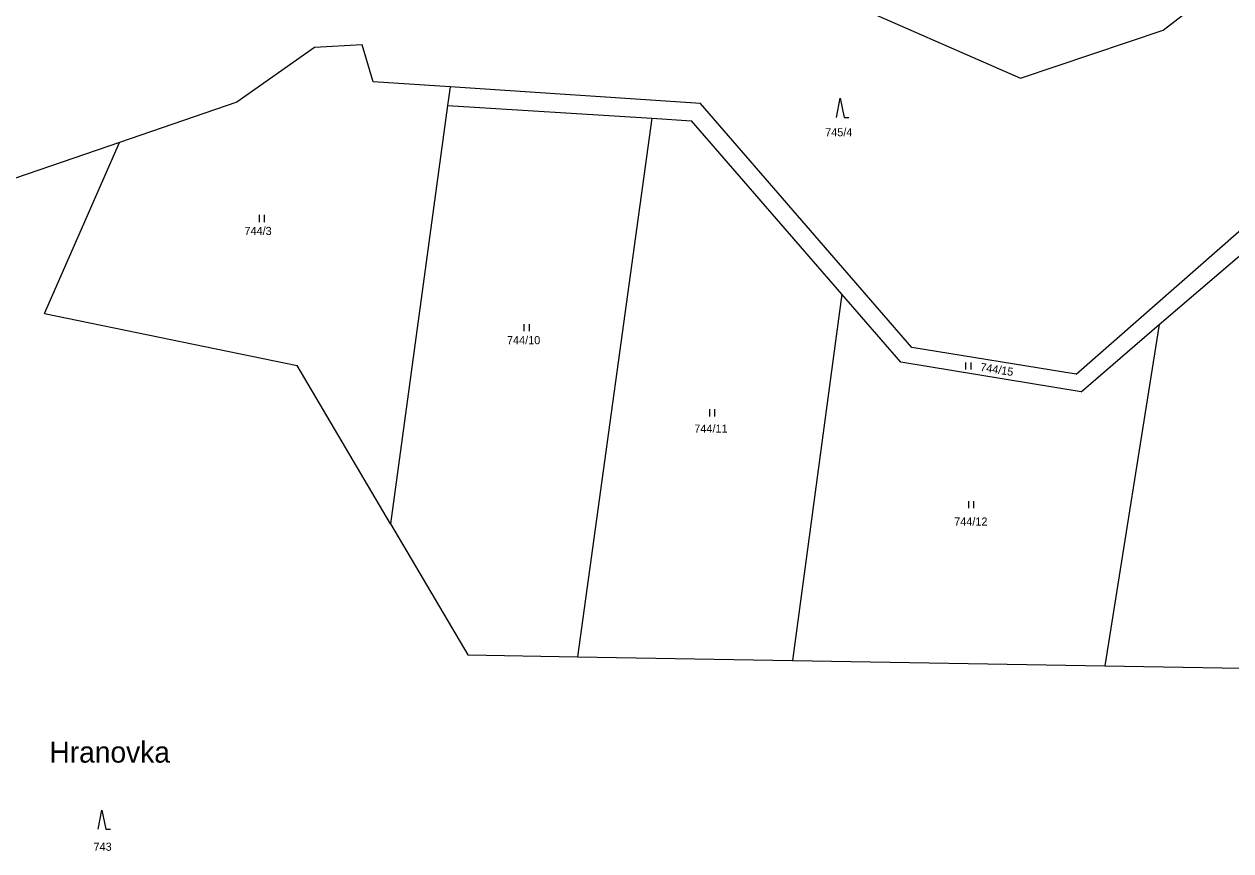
# Model space of a CAD drawing. Extents: x -791032 to -787751, y -1106872 to -1104403.
# Drawn here: x -790542.9 to -790290.7, y -1106219.6 to -1106046.8 of the extents above; entities that cross this region are included whole.
import ezdxf

# ---------------------------------------------------------------- set-up
doc = ezdxf.new("R2010")
doc.units = 0
for name, color, linetype in [('Vrstva 1', 7, 'Continuous'), ('Vrstva 14', 7, 'Continuous'), ('Vrstva 23', 7, 'Continuous'), ('Vrstva 39', 7, 'Continuous')]:
    doc.layers.add(name, color=color, linetype=linetype)

msp = doc.modelspace()

# ---------------------------------------------------------------- linework, layer by layer
at = {"layer": 'Vrstva 1'}
for p, q in [((-790304.82, -1106048.11), (-790223.22, -1105984.47)), ((-790400.09, -1106029.44), (-790334.63, -1106058.1)), ((-790334.63, -1106058.1), (-790304.82, -1106048.11)), ((-790482.18, -1106051.7), (-790498.38, -1106063.11)), ((-790472.21, -1106051.14), (-790482.18, -1106051.7)), ((-790469.92, -1106058.87), (-790472.21, -1106051.14)), ((-790453.84, -1106059.94), (-790469.92, -1106058.87)), ((-790453.84, -1106059.94), (-790454.37, -1106063.84)), ((-790401.53, -1106063.44), (-790453.84, -1106059.94)), ((-790498.38, -1106063.11), (-790522.93, -1106071.55)), ((-790454.37, -1106063.84), (-790466.31, -1106151.23)), ((-790454.37, -1106063.84), (-790411.7, -1106066.5)), ((-790357.33, -1106114.4), (-790401.53, -1106063.44)), ((-790411.7, -1106066.5), (-790427.19, -1106179.06)), ((-790411.7, -1106066.5), (-790403.37, -1106067.02)), ((-790371.96, -1106103.26), (-790403.37, -1106067.02)), ((-790522.93, -1106071.55), (-790547.1, -1106079.85)), ((-790538.62, -1106107.33), (-790522.93, -1106071.55)), ((-790322.97, -1106120.01), (-790272.93, -1106075.97)), ((-790305.62, -1106109.6), (-790273.47, -1106081.99)), ((-790371.96, -1106103.26), (-790382.3, -1106179.84)), ((-790359.66, -1106117.46), (-790371.96, -1106103.26)), ((-790538.62, -1106107.33), (-790485.81, -1106118.18)), ((-790321.96, -1106123.64), (-790305.62, -1106109.6)), ((-790305.62, -1106109.6), (-790316.99, -1106180.96)), ((-790322.97, -1106120.01), (-790357.33, -1106114.4)), ((-790321.96, -1106123.64), (-790359.66, -1106117.46)), ((-790466.31, -1106151.23), (-790485.81, -1106118.18)), ((-790466.31, -1106151.23), (-790450.12, -1106178.67)), ((-790450.12, -1106178.67), (-790427.19, -1106179.06)), ((-790427.19, -1106179.06), (-790382.3, -1106179.84)), ((-790382.3, -1106179.84), (-790316.99, -1106180.96)), ((-790316.99, -1106180.96), (-790288.36, -1106181.45))]:
    msp.add_line(p, q, dxfattribs=at)
at = {"layer": 'Vrstva 23'}
for p, q in [((-790373.09, -1106066.3), (-790372.29, -1106062.3)), ((-790372.29, -1106062.3), (-790371.49, -1106066.3)), ((-790371.49, -1106066.3), (-790370.49, -1106066.3)), ((-790493.7, -1106088.19), (-790493.7, -1106086.69)), ((-790492.7, -1106086.69), (-790492.7, -1106088.19)), ((-790438.33, -1106111.02), (-790438.33, -1106109.52)), ((-790437.33, -1106109.52), (-790437.33, -1106111.02)), ((-790346.04, -1106119.03), (-790346.04, -1106117.53)), ((-790345.04, -1106117.53), (-790345.04, -1106119.03)), ((-790399.59, -1106128.82), (-790399.59, -1106127.32)), ((-790398.59, -1106127.32), (-790398.59, -1106128.82)), ((-790345.45, -1106147.99), (-790345.45, -1106146.49)), ((-790344.45, -1106146.49), (-790344.45, -1106147.99)), ((-790527.4, -1106215.08), (-790526.6, -1106211.08)), ((-790526.6, -1106211.08), (-790525.8, -1106215.08)), ((-790525.8, -1106215.08), (-790524.8, -1106215.08))]:
    msp.add_line(p, q, dxfattribs=at)

# ---------------------------------------------------------------- texts
at = {"layer": 'Vrstva 14'}
for s, p in [('745/4', (-790375.454, -1106070.27)), ('744/3', (-790496.818, -1106090.89)), ('744/10', (-790441.95, -1106113.72)), ('744/11', (-790402.805, -1106132.21)), ('744/12', (-790348.491, -1106151.63)), ('743', (-790528.359, -1106219.59))]:
    msp.add_text(s, height=1.7, dxfattribs=at).set_placement(p)
msp.add_text('744/15', height=1.7, rotation=350.80182, dxfattribs=at).set_placement((-790343.136, -1106119.282))
at = {"layer": 'Vrstva 39'}
msp.add_text('Hranovka', height=4.4, dxfattribs=at).set_placement((-790537.57, -1106201.17))

doc.saveas('drawing.dxf')
